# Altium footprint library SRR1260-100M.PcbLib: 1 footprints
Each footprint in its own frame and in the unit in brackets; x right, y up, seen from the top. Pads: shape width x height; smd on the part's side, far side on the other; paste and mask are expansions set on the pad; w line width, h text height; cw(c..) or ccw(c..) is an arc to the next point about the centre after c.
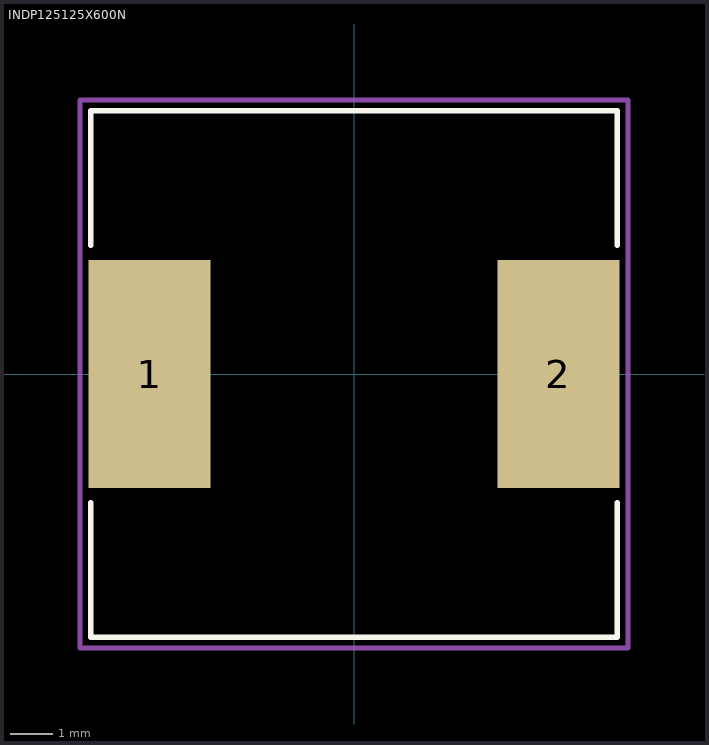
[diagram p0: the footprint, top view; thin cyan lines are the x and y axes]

## INDP125125X600N [mm]
pads (2):
  rect 2.9x5.4 smd: 1(-4.85,0) 2(4.85,0)
Top Overlay:
  lines w0.127: -6.25,-3.05 -6.25,-6.25 6.25,-6.25 6.25,-3.05 ; -6.25,3.05 -6.25,6.25 6.25,6.25 6.25,3.05
Mechanical 15:
  lines w0.127: -6.5,-6.5 -6.5,6.5 6.5,6.5 6.5,-6.5 -6.5,-6.5
3D body "srr1260-100m.stp": height 6, standoff 0, extent -6.25,-6.377 6.25,6.123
